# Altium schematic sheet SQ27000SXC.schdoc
size 127 x 101 mm
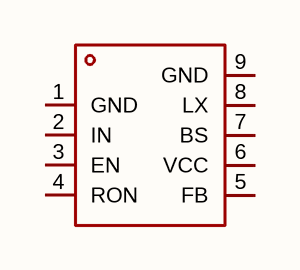
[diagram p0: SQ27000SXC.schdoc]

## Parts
U?  sq27000sxc  [DFN-8_L4.0-W4.0-P0.80-BL-EP]  (value not drawn)

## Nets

Not connected (* = marked no-connect by the designer): U? 1(GND) 2(IN) 3(EN) 4(RON) 5(FB) 6(VCC) 7(BS) 8(LX) 9(GND)

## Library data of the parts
U? = sq27000sxc: 功能类型:降压型;工作电压:7V~100V;输出电压:-;输出电流:600mA;输出类型:可调;; Manufacturer: Silergy(矽力杰); AddInBom: yes; ModelId: 0d6b8adc31b146f3872a44c9163db7e0; ModelName: DFN-8_L4.0-W4.0-H1.0-P0.80; ModelTransform: 158.267,157.48,0,90,0,0,0,0,0; Function: 降压型; Output Current: 600mA; Frequency - Switching: 200kHz~1MHz; Synchronous Rectifier: 是; Number of Outputs: 1; Topology: 降压式; Switch tube (built-in/external): 内置; Output Type: 可调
